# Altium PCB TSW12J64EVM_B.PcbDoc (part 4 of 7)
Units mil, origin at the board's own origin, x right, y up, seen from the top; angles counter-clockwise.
Board outline 8833 x 2680 mil, 10 copper layers (Top Layer L1, Gnd-Plane - L2, Signals - L3, Gnd-Plane - L4, Pwr Plane - L5, Signals - L6, Gnd-Plane - L7, Signals - L8, Gnd-Plane - L9, Bottom Layer - L10), stack 57.8 mil thick; 950 components, 533 nets, 2888 pads, 1732 vias.
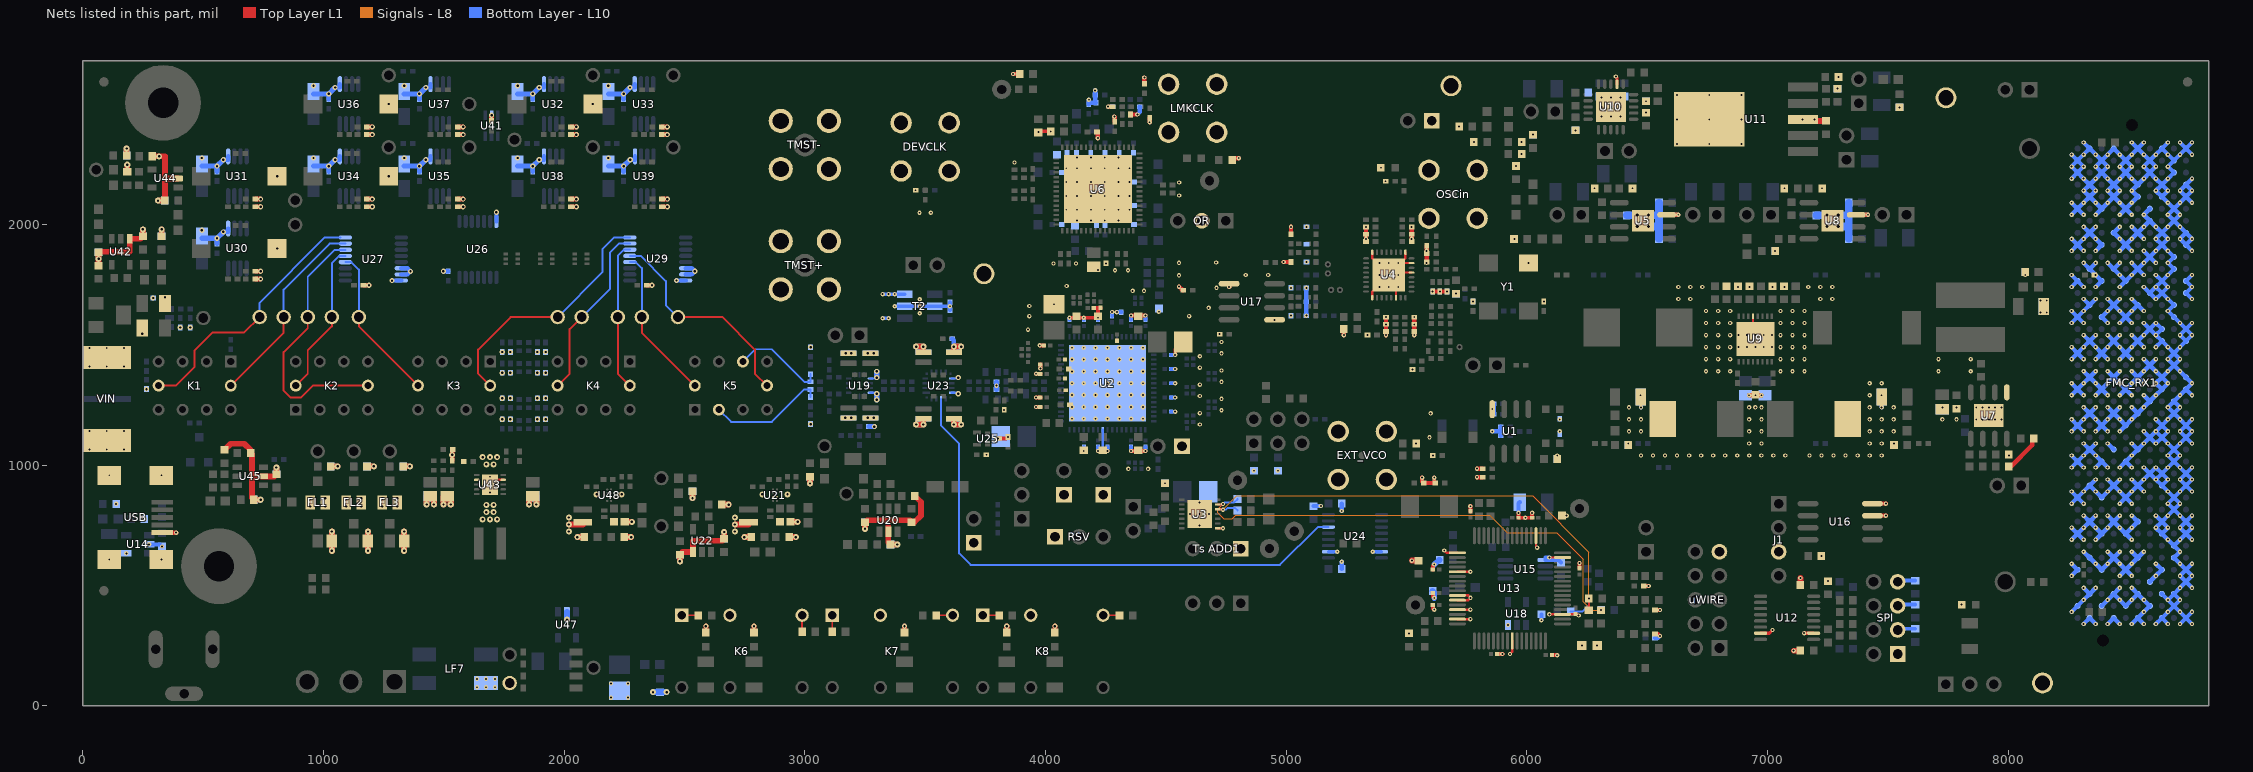
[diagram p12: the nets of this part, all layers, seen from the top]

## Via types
v1: diameter 18, hole 8, Top Layer L1 to Bottom Layer - L10, tented both sides, 1096 vias
v2: diameter 21.46, hole 10, Top Layer L1 to Bottom Layer - L10, tented both sides, 266 vias
v3: diameter 25, hole 10, Top Layer L1 to Bottom Layer - L10, tented both sides, 154 vias
v4: diameter 19.68, hole 7.87, Top Layer L1 to Bottom Layer - L10, 103 vias
v5: diameter 18, hole 8, Top Layer L1 to Bottom Layer - L10, tented bottom, 42 vias
v6: diameter 18, hole 8, Top Layer L1 to Bottom Layer - L10, tented top, 24 vias
v7: diameter 18, hole 8.01, Top Layer L1 to Bottom Layer - L10, tented both sides, 16 vias
v8: diameter 18, hole 8.01, Top Layer L1 to Bottom Layer - L10, tented bottom, 16 vias
v9: diameter 25.98, hole 12.99, Top Layer L1 to Bottom Layer - L10, tented top, 8 vias
v10: diameter 19.68, hole 7.87, Top Layer L1 to Bottom Layer - L10, tented top, 5 vias
v11: diameter 126, hole 106, Top Layer L1 to Bottom Layer - L10, tented top, 2 vias

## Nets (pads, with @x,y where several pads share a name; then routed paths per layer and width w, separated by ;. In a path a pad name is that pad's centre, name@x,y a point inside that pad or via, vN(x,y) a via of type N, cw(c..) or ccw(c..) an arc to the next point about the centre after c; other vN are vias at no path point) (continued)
GND: 1:1.1 2:1.1 5:1.1 12V.2 "1:1 Atten.2" "2:1 Atten.2" "5:1 Atten.2" "AC COUPLED.2" "DC COUPLED.2" "Ts ADD1.1" AC.1 C1.1 C2.2 C8.2 C11.2 C16.1 C18.1 C19.1 C24.2 C25.2 C27.2 C39.2 C40.2 C41.1 C42.1 C43.1 C44.1 C45.1 C46.1 C47.1 C48.2 C49.2 C50.2 C51.1 C52.1 C53.1 C54.1 C55.1 C56.1 C57.1 C58.1 C59.2 C60.2 C61.2 C62.1 C63.1 C64.1 C65.1 C66.1 C67.1 C68.1 C69.1 C70.1 C71.1 C72.2 C73.1 C74.1 C77.2 C78.2 C79.2 C80.2 C81.2 C82.2 C85.1 C88.2 C97.2 C98.2 C100.2 C102.2 C103.2 C104.2 C105.2 C106.2 C107.2 C108.2 C109.2 C110.2 C111.2 C114.1 C115.2 C116.2 C120.2 C121.2 C122.2 C124.2 C125.2 C126.2 C127.2 C128.2 C129.2 C130.2 C143.2 C144.2 C145.2 C146.2 C147.2 C150.2 C151.2 C152.2 C153.2 C155.2 C156.1 C157.1 C158.2 C159.2 C160.2 C161.2 C162.2 C163.2 C164.2 C165.2 C166.2 C167.2 C168.2 C171.2 C172.2 C173.2 C176.2 C177.2 C178.2 C179.2 C180.2 C181.2 C182.2 C183.2 C184.2 C185.2 C186.2 C187.2 C188.2 C189.2 C190.2 C191.2 C193.2 C194.2 C195.2 C196.2 C197.2 C198.2 C199.2 C202.2 C203.2 C204.2 C206.2 C207.2 C208.2 C209.2 C213.2 C215.2 C218.2 C228.2 C229.2 C230.2 C231.1 C232.2 C233.2 C234.2 C235.1 C236.2 C237.2 C238.2 C239.2 C240.2 C241.2 C242.2 C243.2 C250.1 C251.1 C252.2 C253.2 C254.2 C255.2 C256.2 C257.2 C258.1 C259.1 C260.1 C261.2 C264.1 C265.2 C266.2 C267.1 C268.2 C269.1 C270.1 C271.2 C272.1 C276.2 C277.2 C278.2 C280.2 C281.2 C282.2 C283.2 C284.1 C285.1 C287.2 C288.2 C289.2 C290.2 C291.2 C292.1 C297.2 C298.2 C299.2 C300.2 C301.1 C302.2 C303.2 C304.1 C305.2 C306.1 C307.1 C308.2 C309.1 C310.1 C311.2 C312.2 C313.2 C314.2 C315.2 C316.2 C317.2 C318.2 C319.2 C320.2 C321.2 C322.2 C323.2 C324.2 C325.2 C326.2 C327.2 C328.2 C329.2 C330.2 C331.1 C332.1 C333.1 C334.1 C335.1 C336.1 C337.1 C338.1 C339.1 C340.1 C346.2 C347.1 C349.1 C350.2 C351.2 C353.2 C354.2 C355.2 C356.2 C357.2 C358.2 C359.2 C360.2 C361.2 C362.2 C363.2 C364.2 C365.2 C366.2 C367.2 C368.2 C369.2 C370.1 C372.1 C373.1 C375.1 C376.2 C378.2 C379.1 C381.1 C382.2 C383.2 C384.2 C385.2 C386.1 C387.1 C388.1 C389.2 C390.2 C391.2 C392.2 C393.2 C394.1 C395.2 C396.2 C397.1 C398.2 C399.2 C400.1 C401.2 C402.2 C404.2 C405.2 C406.2 C407.2 C408.2 C410.2 C411.2 C413.2 C414.1 C415.2 C416.2 C418.1 C419.1 D5.2 D6.2 DC.1 DEVCLK.2 DEVCLK.3 DEVCLK.4 DEVCLK.5 EXT_Vcmo.1 EXT_VCO.2 EXT_VCO.3 EXT_VCO.4 EXT_VCO.5 FL1.2 FL2.2 FL3.2 FMC_RX1.A1 FMC_RX1.A4 FMC_RX1.A5 FMC_RX1.A8 FMC_RX1.A9 FMC_RX1.A12 FMC_RX1.A13 FMC_RX1.A16 FMC_RX1.A17 FMC_RX1.A20 FMC_RX1.A21 FMC_RX1.A24 FMC_RX1.A25 FMC_RX1.A28 FMC_RX1.A29 FMC_RX1.A32 FMC_RX1.A33 FMC_RX1.A36 FMC_RX1.A37 FMC_RX1.A40 FMC_RX1.B2 FMC_RX1.B3 FMC_RX1.B6 FMC_RX1.B7 FMC_RX1.B10 FMC_RX1.B11 FMC_RX1.B14 FMC_RX1.B15 FMC_RX1.B18 FMC_RX1.B19 FMC_RX1.B22 FMC_RX1.B23 FMC_RX1.B26 FMC_RX1.B27 FMC_RX1.B30 FMC_RX1.B31 FMC_RX1.B34 FMC_RX1.B35 FMC_RX1.B38 FMC_RX1.B39 FMC_RX1.C1 FMC_RX1.C4 FMC_RX1.C5 FMC_RX1.C8 FMC_RX1.C9 FMC_RX1.C12 FMC_RX1.C13 FMC_RX1.C16 FMC_RX1.C17 FMC_RX1.C20 FMC_RX1.C21 FMC_RX1.C24 FMC_RX1.C25 FMC_RX1.C28 FMC_RX1.C29 FMC_RX1.C32 FMC_RX1.C33 FMC_RX1.C36 FMC_RX1.C38 FMC_RX1.C40 FMC_RX1.D2 FMC_RX1.D3 FMC_RX1.D6 FMC_RX1.D7 FMC_RX1.D10 FMC_RX1.D13 FMC_RX1.D16 FMC_RX1.D19 FMC_RX1.D22 FMC_RX1.D25 FMC_RX1.D28 FMC_RX1.D37 FMC_RX1.D39 FMC_RX1.E1 FMC_RX1.E4 FMC_RX1.E5 FMC_RX1.E8 FMC_RX1.E11 FMC_RX1.E14 FMC_RX1.E17 FMC_RX1.E20 FMC_RX1.E23 FMC_RX1.E26 FMC_RX1.E29 FMC_RX1.E32 FMC_RX1.E35 FMC_RX1.E38 FMC_RX1.E40 FMC_RX1.F2 FMC_RX1.F3 FMC_RX1.F6 FMC_RX1.F9 FMC_RX1.F12 FMC_RX1.F15 FMC_RX1.F18 FMC_RX1.F21 FMC_RX1.F24 FMC_RX1.F27 FMC_RX1.F30 FMC_RX1.F33 FMC_RX1.F36 FMC_RX1.F39 FMC_RX1.G1 FMC_RX1.G4 FMC_RX1.G5 FMC_RX1.G8 FMC_RX1.G11 FMC_RX1.G14 FMC_RX1.G17 FMC_RX1.G20 FMC_RX1.G23 FMC_RX1.G26 FMC_RX1.G29 FMC_RX1.G32 FMC_RX1.G35 FMC_RX1.G38 FMC_RX1.G40 FMC_RX1.H2 FMC_RX1.H3 FMC_RX1.H6 FMC_RX1.H9 FMC_RX1.H12 FMC_RX1.H15 FMC_RX1.H18 FMC_RX1.H21 FMC_RX1.H24 FMC_RX1.H27 FMC_RX1.H30 FMC_RX1.H33 FMC_RX1.H36 FMC_RX1.H39 FMC_RX1.J1 FMC_RX1.J4 FMC_RX1.J5 FMC_RX1.J8 FMC_RX1.J11 FMC_RX1.J14 FMC_RX1.J17 FMC_RX1.J20 FMC_RX1.J23 FMC_RX1.J26 FMC_RX1.J29 FMC_RX1.J32 FMC_RX1.J35 FMC_RX1.J38 FMC_RX1.J40 FMC_RX1.K2 FMC_RX1.K3 FMC_RX1.K6 FMC_RX1.K9 FMC_RX1.K12 FMC_RX1.K15 FMC_RX1.K18 FMC_RX1.K21 FMC_RX1.K24 FMC_RX1.K27 FMC_RX1.K30 FMC_RX1.K33 FMC_RX1.K36 FMC_RX1.K39 GND1.1 GND2.1 GND3.1 GND4.1 GND.1 J1.3 K6.3 K7.3 K8.3 L23.2 L37.2 L41.2 LD.2 LF2.2 LF3.1 LF7.4 LMKCLK.2 LMKCLK.3 LMKCLK.4 LMKCLK.5 OR.2 OSCin.2 OSCin.3 OSCin.4 OSCin.5 R2.2 R3.1 R4.1 R5.1 R6.1 R10.2 R11.1 R12.1 R22.2 R23.2 R24.1 R26.1 R29.1 R30.1 R33.1 R36.1 R37.1 R45.1 R49.1 R50.2 R51.1 R56.1 R65.1 R76.1 R77.1 R86.1 R87.1 R88.1 R89.1 R90.1 R96.1 R104.1 R116.1 R122.1 R128.1 R129.1 R135.1 R139.1 R140.1 R141.1 R147.2 R152.2 R153.1 R158.1 R159.1 R165.1 R168.1 R172.1 R177.1 R186.1 R191.1 R193.1 R194.1 R196.1 R197.2 R199.2 R200.1 R202.1 R204.1 R232.1 R244.1 R247.1 R249.1 RSV.1 SPI.1 SPI.3 SPI.5 SPI.7 T2.1 T2.2 T2.5 TMST+.2 TMST+.3 TMST+.4 TMST+.5 TMST-.2 TMST-.3 TMST-.4 TMST-.5 U1.4 U2.61 U2.69 U3.8 U3.15 U4.1 U4.8 U4.17 U4.22 U4.29 U4.31 U4.33 U5.3 U5.9 U6.65 U7.5 U7.9 U8.3 U8.9 U9.5 U9.17 U10.12 U10.21 U11.3 U11.6 U12.7 U12.10 U16.3 U16.4 U17.1 U17.5 U18.3 U19.11 U19.14 U20.2 U21.C1 U21.C2 U22.1 U23.9 U23.12 U24.7 U24.10 U25.2 U26.7 U27.6 U27.7 U27.8 U29.6 U29.7 U29.8 U30.1 U31.1 U32.1 U33.1 U34.1 U35.1 U36.1 U37.1 U38.1 U39.1 U41.2 U42.1 U43.4 U43.7 U43.11 U44.2 U45.2 U47.2 U48.C1 U48.C2 uWIRE.9 VA12.1 VA19.1 Vbg.1 VD12.1 VIN.2 VIN.3 VIN.4 VIN.5 Y1.2 | length 31586
  Top Layer L1 w7: v3(3462.62,1168.6) C301.1@3462.62,1192.1 ; C307.1@3462.62,1468.22 v3(3462.62,1491.72) ; v3(3649.14,1168.6) C302.2@3649.14,1192.1 ; C308.2@3649.14,1468.22 v3(3649.14,1491.72)
  Top Layer L1 w9: U3.8@4715.08,737.7 v1(4737.28,737.7)
  Top Layer L1 w9.45: U43.11@1692,919 1711.68,938.68 U43.4@1747.12,938.68 ; U4.17@5357.34,1695.51 5357.34,1721.1 v4(5426.24,1790) ; U4.8@5357.34,1884.49 5357.34,1858.9 v4(5426.24,1790) ; U4.33@5436.08,1799.84 U4.29@5520.72,1799.84 ; U4.22@5455.76,1695.51 U4.33@5455.76,1760.47 ; U4.33@5475.45,1839.21 U4.31@5520.72,1839.21 ; U4.1@5495.13,1884.49 5495.13,1858.9 v4(5426.24,1790)
  Top Layer L1 w10: U9.5@6939.16,1618.49 6939.16,1553.53 U9.17@6949,1543.68
  Top Layer L1 w11.02: v4(5426.24,1790) U4.33@5455.76,1760.47
  Top Layer L1 w13: U12.7@6970.76,301.55 7007.03,301.55 v1(7020.48,315) ; v1(7151.68,301.55) U12.10@7191.24,301.55
  Top Layer L1 w13.5: v1(6369.77,2614.17) 6374.27,2609.67 U10.12@6374.27,2582.49
  Top Layer L1 w15: v1(3970.3,2383.18) 3973.86,2386.74 v1(4021.74,2386.74)
  Top Layer L1 w15.75: v1(3803.41,1110) 3837.23,1110 v1(3844.12,1116.89)
  Top Layer L1 w16: v1(3961.03,1241.58) C51.1@3978.65,1241.57 ; v1(3961.03,1280.95) C41.1@3978.65,1280.94 ; v1(3961.03,1379.37) C42.1@3978.65,1379.37 ; v1(3976.03,1497.48) C44.1@3993.65,1497.48 ; v1(3978.65,1401.47) C54.1@3978.65,1418.74 ; v1(4099.91,1612) v1(4218.02,1612) ; R22.2@4200.99,1653 R23.2@4229,1653.01 ; v1(4218.02,1058.65) v1(4257.39,1058.65) ; C50.2@4218.02,1618.3 4218.02,1653 ; v1(4355.81,1058.65) v1(4414.87,1058.65) ; v1(4355.81,1621.35) v1(4414.87,1621.35) ; v1(4538.74,1458.11) 4538.74,1477.62 C72.2@4572.52,1511.4
  Top Layer L1 w16.5: R116.1@6484.93,498 v1(6505.98,498) ; R128.1@6531.81,298 6544.87,298 v1(6552.87,290) ; R104.1@6531.81,398 v1(6552.87,398) ; U16.3@7435.86,790 v1(7491.16,790) ; U16.4@7435.86,840 v1(7491.16,840)
  Top Layer L1 w18: v1(3865.3,2625) R45.1@3892.94,2625 ; C85.1@4213.69,2384 4217.56,2380.13 v1(4217.56,2358.32) ; v1(4260.43,2489) R50.2@4279.3,2489 ; v1(4286.16,2447.5) 4288,2445.65 C88.2@4288,2426.69 ; C114.1@4352.67,2456.68 v1(4381.54,2456.69) ; C259.1@4410.91,2584.24 v1(4410.91,2610.11) ; v1(4432.67,2424.26) R51.1@4432.67,2443.13 ; v1(4554.36,1741.48) 4569.84,1726 C215.2@4572.31,1726 ; v1(4762.84,1740) U17.5@4762.84,1753.5 ; R56.1@4775.06,2274.95 v1(4802.7,2274.95) ; v1(4989.23,1843.81) R36.1@5020.05,1843.81 ; R29.1@5020.05,1959.18 v1(5020.05,1990) ; v1(5239.44,1540) R152.2@5239.44,1565 ; C257.2@5331.35,1929.09 C256.2@5331.35,1959.09 v1(5331.35,1989.09) ; v1(5414.55,1540) C243.2@5414.55,1554.68 v1(5414.55,1614.68) ; C254.2@5521.12,1929.09 C253.2@5521.12,1959.09 v1(5521.12,1989.09) ; v1(5531.92,1540) C240.2@5531.92,1554.68 v1(5531.92,1614.68) ; v1(5608.33,1721.1) v1(5668.33,1721.1) ; v1(5792.82,950) R11.1@5816.63,950 ; v1(5792.82,985) C8.2@5816.63,985 ; U5.3@6580.43,2040 v1(6628.8,2040) ; v1(6923.47,1290) v1(6974.53,1290) ; U8.3@7368.43,2040 v1(7416.8,2040) ; R76.1@8002.56,995 8012,995 8099,1082 8099,1101.98 C162.2@8106.56,1109.54
  Top Layer L1 w19.68: C321.2@716.69,1773.13 v2(739.23,1773.13) ; C311.2@716.69,1805 v2(739.23,1805) ; C322.2@716.69,2073.13 v2(739.23,2073.13) ; C312.2@716.69,2105 v2(739.23,2105) ; C347.1@1166.68,1746.84 v2(1189.23,1746.84) ; C325.2@1180.69,2073.13 v2(1203.23,2073.13) ; C315.2@1180.69,2105 v2(1203.23,2105) ; C327.2@1180.69,2373.13 v2(1203.23,2373.13) ; C317.2@1180.69,2405 v2(1203.23,2405) ; R244.1@1535,1018.37 v3(1535,1042.68) 1535,1062.97 C385.2@1537.06,1065.02 ; C326.2@1557.69,2073.13 v2(1580.23,2073.13) ; C316.2@1557.69,2105 v2(1580.23,2105) ; C328.2@1557.69,2373.13 v2(1580.23,2373.13) ; C318.2@1557.69,2405 v2(1580.23,2405) ; C355.2@1698.58,2429.69 v2(1698.58,2453.4) ; C329.2@2028.69,2073.13 v2(2051.23,2073.13) ; C319.2@2028.69,2105 v2(2051.23,2105) ; C323.2@2028.69,2373.13 v2(2051.23,2373.13) ; C313.2@2028.69,2405 v2(2051.23,2405) ; C349.1@2342.68,1746.84 v2(2365.23,1746.84) ; C324.2@2405.69,2373.13 v2(2428.23,2373.13) ; C314.2@2405.69,2405 v2(2428.23,2405) ; C330.2@2406.69,2073.13 v2(2429.23,2073.13) ; C320.2@2406.69,2105 v2(2429.23,2105) ; C251.1@5583.65,1844 R30.1@5583.65,1911.41
  Top Layer L1 w21.46: 2589,304.53 v2(2589,331.01) ; 2789,304.53 v2(2789,331.01) ; 3414,304.53 v2(3414,331.01) ; 3839,304.53 v2(3839,331.01) ; 4039,304.53 v2(4039,331.01)
  Top Layer L1 w22: v3(3492.62,1168.6) C301.1@3492.62,1192.1 ; C307.1@3492.62,1468.22 v3(3492.62,1491.72) ; v3(3619.14,1168.6) C302.2@3619.15,1192.09 ; C308.2@3619.15,1468.22 v3(3619.14,1491.72)
  Top Layer L1 w23.62: C357.2@66,1886 195.4,1886 U42.1@195.4,1940.13 239.37,1940.13 C359.2@250,1950.76 ; R247.1@289.23,2283 342,2283 342,2191 ; C390.2@342,2099 342,2191 ; U44.2@396.13,2191 342,2191
  Top Layer L1 w24: R232.1@66,1828.52 v3(66,1856.77) C357.2@66,1885.02 ; C392.2@182.12,2286.98 v3(182.12,2315.23) ; C393.2@185,2219.54 v3(185,2247.79) ; C359.2@250,1950.76 v3(250,1979.01) ; v3(312.77,2099) C390.2@341.02,2099 ; C405.2@328,1950.76 v3(328,1979.01) ; R249.1@589.11,1063.56 614.55,1089 671.18,1089 697.98,1062.2 C408.2@697.98,1050 703,1044.98 703,863.87 C411.2@710.87,856 v3(739.12,856) ; 703,953 U45.2@751.13,953 796.03,953 C407.2@804.89,961.86 v3(804.89,990.11) ; C396.2@1031.12,995 v3(1059.37,995) ; C402.2@1181.12,995 v3(1209.37,995) ; C399.2@1331.12,995 v3(1359.37,995) ; v3(2055.37,701.02) C418.1@2083.62,701.02 ; C419.1@2250.36,701.02 v3(2278.6,701.02) ; C415.2@2251.99,764.47 v3(2281.22,764.47) ; v3(2481,599.88) C300.2@2481,628.13 2491.63,638.76 U22.1@2535.6,638.76 2535.6,686 2657.13,686 C288.2@2665,693.87 v3(2665,722.12) ; v3(2533.47,862.65) C289.2@2533.47,890.9 ; R177.1@2655.68,836 v3(2683.93,836) ; v3(2749.18,701.02) C284.1@2777.43,701.02 ; C285.1@2934.55,701.02 v3(2962.8,701.02) ; C282.2@2940.99,764.46 v3(2970.22,764.46) ; v3(3021.57,923.6) C281.2@3021.57,951.85 ; v3(3250,734.88) C298.2@3250,763.13 3257.87,771 3347,771 ; v3(3384.11,670) C277.2@3355.86,670 3347,678.86 U20.2@3347,723.76 3347,771 ; R172.1@3457.56,872 3483,846.56 3483,789.93 3456.2,763.13 C278.2@3444,763.13 3436.13,771 3347,771 ; v1(7108.37,229) R65.1@7136.12,229 ; C129.2@7136.12,502.06 v1(7136.12,530.79) ; U11.3@7147.22,2436 7153.13,2430.09 C196.2@7243,2430.09
  Top Layer L1 w25: v3(1035.06,644.11) C394.1@1035.06,684.17 v3(1035.06,724.23) ; v3(1185.05,644.11) C400.1@1185.05,684.17 v3(1185.05,724.23) ; v3(1335.05,644.11) C397.1@1335.05,684.17 v3(1335.05,724.23) ; v3(1428.94,836.32) C387.1@1428.94,870.47 ; v3(1459.06,836.32) C387.1@1459.06,870.47 ; v3(1498.94,836.32) C386.1@1498.94,870.47 ; v3(1529.06,836.32) C386.1@1529.06,870.47 ; v3(1854.94,836.32) C383.2@1854.94,870.47 ; v3(1885.06,836.32) C383.2@1885.06,870.47 ; v3(2019.99,753.16) L41.2@2077.49,753.16 ; v3(2708.99,753.16) L37.2@2766.49,753.16 ; v3(3462.62,1168.6) v3(3492.62,1168.6) ; v3(3462.62,1491.72) v3(3492.62,1491.72) ; v3(3619.14,1168.6) v3(3649.14,1168.6) ; v3(3619.14,1491.72) v3(3649.14,1491.72)
  Bottom Layer - L10 w7: v3(3462.62,1168.6) C303.2@3462.62,1192.1 ; C305.2@3462.62,1468.22 v3(3462.62,1491.72) ; v3(3649.14,1168.6) C304.1@3649.14,1192.1 ; C306.1@3649.14,1468.22 v3(3649.14,1491.72)
  Bottom Layer - L10 w9: 4237.7,1058.65 U2.61@4237.7,1147.09
  Bottom Layer - L10 w9.84: U19.14@3272.5,1300.63 3295.01,1300.63 v2(3298.98,1296.66) ; U19.11@3272.5,1359.68 3295.01,1359.68 v2(3298.98,1363.65) ; U23.12@3611,1300.63 3633.51,1300.63 v2(3637.48,1296.66) ; U23.9@3611,1359.68 3633.51,1359.68 v2(3637.48,1363.65)
  Bottom Layer - L10 w13: U24.10@5175.57,640.02 v1(5212.13,640.02) ; v1(5359.49,640.02) U24.7@5396.05,640.02
  Bottom Layer - L10 w16: v1(3323.58,1609.95) v1(3348.58,1609.95) ; v1(3323.58,1709.95) T2.1@3415.06,1709.95 ; v1(3373.58,1659.95) v1(3602.85,1659.95) ; C229.2@3602.85,1643.14 v1(3602.85,1659.95) ; C228.2@3602.85,1676.76 v1(3602.85,1659.95) ; C45.1@4099.91,1603.73 v1(4099.91,1612) ; v1(4158.96,1058.65) C47.1@4158.96,1076.27 ; C46.1@4158.96,1603.73 v1(4158.96,1612) ; C58.1@4218.02,1076.27 v1(4218.02,1058.65) v1(4257.39,1058.65) C57.1@4257.39,1076.27 ; C55.1@4218.02,1603.73 v1(4218.02,1612) ; C56.1@4277.07,1618.73 v1(4277.07,1636.35) ; v1(4296.16,1635.31) C16.1@4315,1635.31 ; v1(4355.81,1058.65) C62.1@4355.81,1076.27 ; C70.1@4355.81,1603.73 v1(4355.81,1621.35) ; v1(4414.87,1058.65) C63.1@4414.87,1076.27 ; C69.1@4414.87,1603.73 v1(4414.87,1621.35) ; C64.1@4521.12,1221.89 v1(4538.74,1221.89) ; C65.1@4521.12,1280.95 v1(4538.74,1280.94) ; C66.1@4521.12,1340 v1(4538.74,1340) ; C67.1@4521.12,1399.05 v1(4538.74,1399.05) ; C68.1@4521.12,1458.11 v1(4538.74,1458.11) ; SPI.3@7540,315 7545.12,320.12 R139.1@7613.44,320.12 ; SPI.5@7540,415 7545.12,420.12 R140.1@7613.44,420.12 ; SPI.7@7540,515 7545.12,520.12 R141.1@7613.44,520.12
  Bottom Layer - L10 w16.5: v1(6060,355.39) C213.2@6060,380.13 ; R129.1@6531.81,282 6544.87,282 v1(6552.87,290)
  Bottom Layer - L10 w17.72: v2(584.66,1968.88) 604.25,1968.88 U30.1@604.25,1982.68 ; v2(584.66,2268.88) 604.25,2268.88 U31.1@604.25,2282.68 ; v2(1048.66,2268.88) 1068.25,2268.88 U34.1@1068.25,2282.68 ; v2(1048.66,2568.88) 1068.25,2568.88 U36.1@1068.25,2582.68 ; v2(1285.13,1766.43) U27.8@1323.43,1766.43 ; U27.7@1323.43,1792.02 1348.92,1792.02 v2(1361.72,1804.82) 1348.92,1817.61 U27.6@1323.43,1817.61 ; v2(1425.66,2268.88) 1445.25,2268.88 U35.1@1445.25,2282.68 ; v2(1425.66,2568.88) 1445.25,2568.88 U37.1@1445.25,2582.68 ; U26.7@1718.77,2012.14 v2(1718.77,2050.43) ; v2(1896.66,2268.88) 1916.25,2268.88 U38.1@1916.25,2282.68 ; v2(1896.66,2568.88) 1916.25,2568.88 U32.1@1916.25,2582.68 ; v2(2273.66,2568.88) 2293.25,2568.88 U33.1@2293.25,2582.68 ; v2(2274.66,2268.88) 2294.25,2268.88 U39.1@2294.25,2282.68 ; v2(2466.99,1766.87) U29.8@2505.28,1766.87 ; U29.7@2505.28,1792.46 2530.78,1792.46 v2(2543.57,1805.25) 2530.78,1818.05 U29.6@2505.28,1818.05
  Bottom Layer - L10 w18: C107.2@4179.92,2498.87 v1(4179.92,2517.74) ; C107.2@4179.92,2505.74 C104.2@4210.05,2505.74 4206.31,2509.47 C260.1@4206.31,2537.87 v1(4206.32,2556.74) ; v1(4260.43,2489) R159.1@4279.3,2489 ; v1(4381.54,2456.69) 4392.04,2467.19 R158.1@4392.04,2489 ; C98.2@5113.28,829.84 v1(5143.83,829.84) ; R186.1@5230.69,568 v1(5230.69,598.54) ; v1(5230.69,809.46) C97.2@5230.69,840 ; v1(6474,1240) C183.2@6474,1290 ; 6548.93,2040 v1(6628.8,2040) ; 7336.93,2040 v1(7416.8,2040) ; v1(7473.85,1240) v1(7473.85,1290) ; v1(8263,390) FMC_RX1.K39@8288,415 v1(8313,440) FMC_RX1.J38@8338,465 ; v1(8263,540) FMC_RX1.K36@8288,565 v1(8263,590) ; v1(8263,690) FMC_RX1.K33@8288,715 ; v1(8263,740) FMC_RX1.K33@8288,715 ; v1(8263,840) FMC_RX1.K30@8288,865 ; v1(8263,890) FMC_RX1.K30@8288,865 ; v1(8263,990) FMC_RX1.K27@8288,1015 ; v1(8263,1040) FMC_RX1.K27@8288,1015 ; v1(8263,1140) FMC_RX1.K24@8288,1165 ; v1(8263,1190) FMC_RX1.K24@8288,1165 ; v1(8263,1290) FMC_RX1.K21@8288,1315 ; v1(8263,1340) FMC_RX1.K21@8288,1315 ; v1(8263,1440) FMC_RX1.K18@8288,1465 ; v1(8263,1490) FMC_RX1.K18@8288,1465 ; v1(8263,1590) FMC_RX1.K15@8288,1615 ; v1(8263,1640) FMC_RX1.K15@8288,1615 ; v1(8263,1740) FMC_RX1.K12@8288,1765 ; v1(8263,1790) FMC_RX1.K12@8288,1765 ; v1(8263,1890) FMC_RX1.K9@8288,1915 ; v1(8263,1940) FMC_RX1.K9@8288,1915 ; v1(8263,2040) FMC_RX1.K6@8288,2065 ; v1(8263,2090) FMC_RX1.K6@8288,2065 ; v1(8263,2190) FMC_RX1.K3@8288,2215 ; v1(8263,2290) FMC_RX1.K2@8288,2265 ; v1(8313,340) FMC_RX1.J40@8338,365 v1(8363,340) ; v1(8313,490) FMC_RX1.J38@8338,465 ; v1(8313,640) FMC_RX1.J35@8338,615 v1(8363,590) FMC_RX1.H36@8388,565 v1(8413,590) FMC_RX1.G35@8438,615 ; v1(8313,690) FMC_RX1.K33@8288,715 ; v1(8313,790) FMC_RX1.J32@8338,765 ; v1(8313,840) FMC_RX1.K30@8288,865 ; v1(8313,990) FMC_RX1.K27@8288,1015 ; v1(8313,1090) FMC_RX1.J26@8338,1065 ; v1(8313,1140) FMC_RX1.K24@8288,1165 ; v1(8313,1240) FMC_RX1.J23@8338,1215 ; v1(8313,1290) FMC_RX1.K21@8288,1315 ; v1(8313,1390) FMC_RX1.J20@8338,1365 ; v1(8313,1440) FMC_RX1.K18@8288,1465 ; v1(8313,1540) FMC_RX1.J17@8338,1515 ; v1(8313,1590) FMC_RX1.K15@8288,1615 ; v1(8313,1690) FMC_RX1.J14@8338,1665 ; v1(8313,1740) FMC_RX1.K12@8288,1765 ; v1(8313,1840) FMC_RX1.J11@8338,1815 ; v1(8313,1890) FMC_RX1.K9@8288,1915 ; v1(8313,1990) FMC_RX1.J8@8338,1965 ; v1(8313,2040) FMC_RX1.K6@8288,2065 ; v1(8313,2340) FMC_RX1.J1@8338,2315 ; v1(8363,490) FMC_RX1.J38@8338,465 ; v1(8363,690) FMC_RX1.H33@8388,715 ; v1(8363,790) FMC_RX1.J32@8338,765 ; v1(8363,940) FMC_RX1.J29@8338,915 ; v1(8363,990) FMC_RX1.H27@8388,1015 ; v1(8363,1090) FMC_RX1.J26@8338,1065 ; v1(8363,1140) FMC_RX1.H24@8388,1165 ; v1(8363,1240) FMC_RX1.J23@8338,1215 ; v1(8363,1290) FMC_RX1.H21@8388,1315 ; v1(8363,1390) FMC_RX1.J20@8338,1365 ; v1(8363,1440) FMC_RX1.H18@8388,1465 ; v1(8363,1540) FMC_RX1.J17@8338,1515 ; v1(8363,1690) FMC_RX1.J14@8338,1665 ; v1(8363,1740) FMC_RX1.H12@8388,1765 v1(8363,1790) FMC_RX1.J11@8338,1815 ; v1(8363,1840) FMC_RX1.J11@8338,1815 ; v1(8363,1890) FMC_RX1.H9@8388,1915 v1(8363,1940) FMC_RX1.J8@8338,1965 ; v1(8363,1990) FMC_RX1.J8@8338,1965 ; v1(8363,2040) FMC_RX1.H6@8388,2065 ; FMC_RX1.H39@8388,415 v1(8413,440) FMC_RX1.G38@8438,465 ; v1(8413,340) FMC_RX1.G40@8438,365 v1(8463,340) ; v1(8413,640) FMC_RX1.G35@8438,615 ; v1(8413,790) FMC_RX1.G32@8438,765 ; v1(8413,940) FMC_RX1.G29@8438,915 ; v1(8413,990) FMC_RX1.H27@8388,1015 ; v1(8413,1090) FMC_RX1.G26@8438,1065 ; v1(8413,1140) FMC_RX1.H24@8388,1165 ; v1(8413,1240) FMC_RX1.G23@8438,1215 ; v1(8413,1290) FMC_RX1.H21@8388,1315 ; v1(8413,1390) FMC_RX1.G20@8438,1365 ; v1(8413,1440) FMC_RX1.H18@8388,1465 ; v1(8413,1540) FMC_RX1.G17@8438,1515 ; v1(8413,1590) FMC_RX1.H15@8388,1615 v1(8413,1640) FMC_RX1.G14@8438,1665 ; v1(8413,1690) FMC_RX1.G14@8438,1665 ; v1(8413,1840) FMC_RX1.G11@8438,1815 ; v1(8463,490) FMC_RX1.G38@8438,465 ; v1(8463,540) FMC_RX1.F36@8488,565 ; v1(8463,640) FMC_RX1.G35@8438,615 ; v1(8463,790) FMC_RX1.G32@8438,765 ; v1(8463,840) FMC_RX1.F30@8488,865 ; v1(8463,940) FMC_RX1.G29@8438,915 ; v1(8463,990) FMC_RX1.F27@8488,1015 ; v1(8463,1140) FMC_RX1.F24@8488,1165 ; v1(8463,1240) FMC_RX1.G23@8438,1215 ; v1(8463,1290) FMC_RX1.F21@8488,1315 ; v1(8463,1390) FMC_RX1.G20@8438,1365 ; v1(8463,1440) FMC_RX1.F18@8488,1465 ; v1(8463,1540) FMC_RX1.G17@8438,1515 ; v1(8463,1590) FMC_RX1.F15@8488,1615 ; v1(8463,1690) FMC_RX1.G14@8438,1665 ; v1(8463,1740) FMC_RX1.F12@8488,1765 ; v1(8463,1840) FMC_RX1.G11@8438,1815 ; v1(8463,1890) FMC_RX1.F9@8488,1915 ; v1(8463,1990) FMC_RX1.G8@8438,1965 v1(8463,1940) FMC_RX1.F9@8488,1915 ; v1(8463,2040) FMC_RX1.F6@8488,2065 ; FMC_RX1.F9@8486,1913 v1@8511,1938 ; v1(8513,340) FMC_RX1.E40@8538,365 ; v1(8513,490) FMC_RX1.E38@8538,465 ; v1(8513,540) FMC_RX1.F36@8488,565 ; v1(8513,640) FMC_RX1.E35@8538,615 ; v1(8513,690) FMC_RX1.F33@8488,715 ; v1(8513,790) FMC_RX1.E32@8538,765 v1(8513,740) FMC_RX1.F33@8488,715 ; v1(8513,840) FMC_RX1.F30@8488,865 ; v1(8513,940) FMC_RX1.E29@8538,915 ; v1(8513,990) FMC_RX1.F27@8488,1015 ; v1(8513,1090) FMC_RX1.E26@8538,1065 ; v1(8513,1240) FMC_RX1.E23@8538,1215 ; v1(8513,1290) FMC_RX1.F21@8488,1315 ; v1(8513,1390) FMC_RX1.E20@8538,1365 ; v1(8513,1440) FMC_RX1.F18@8488,1465 ; v1(8513,1540) FMC_RX1.E17@8538,1515 ; v1(8513,1590) FMC_RX1.F15@8488,1615 ; v1(8513,1690) FMC_RX1.E14@8538,1665 ; v1(8513,1840) FMC_RX1.E11@8538,1815 ; v1(8513,1890) FMC_RX1.F9@8488,1915 ; v1(8513,1940) FMC_RX1.E8@8538,1965 ; v1(8513,1990) FMC_RX1.E8@8538,1965 ; v1(8513,2040) FMC_RX1.F6@8488,2065 ; v1(8513,2340) FMC_RX1.E1@8538,2315 ; v1(8563,340) FMC_RX1.E40@8538,365 ; v1(8563,640) FMC_RX1.E35@8538,615 ; v1(8563,890) FMC_RX1.E29@8538,915 ; v1(8563,990) FMC_RX1.D28@8588,965 ; v1(8563,1140) FMC_RX1.D25@8588,1115 ; v1(8563,1290) FMC_RX1.D22@8588,1265 ; v1(8563,1340) FMC_RX1.E20@8538,1365 ; v1(8563,1440) FMC_RX1.D19@8588,1415 ; v1(8563,1490) FMC_RX1.E17@8538,1515 ; v1(8563,1590) FMC_RX1.D16@8588,1565 ; v1(8563,1640) FMC_RX1.E14@8538,1665 ; v1(8563,1740) FMC_RX1.D13@8588,1715 ; v1(8563,1790) FMC_RX1.E11@8538,1815 ; v1(8563,1890) FMC_RX1.D10@8588,1865 ; v1(8563,1940) FMC_RX1.E8@8538,1965 ; v1(8563,2340) FMC_RX1.E1@8538,2315 ; FMC_RX1.D37@8588,515 v1(8613,540) FMC_RX1.C36@8638,565 v1(8613,590) ; FMC_RX1.D6@8588,2065 v1(8563,2040) FMC_RX1.D7@8588,2015 ; v1(8613,340) FMC_RX1.C40@8638,365 ; v1(8613,790) FMC_RX1.C32@8638,765 ; v1(8613,1140) FMC_RX1.D25@8588,1115 ; v1(8613,1190) FMC_RX1.C24@8638,1165 ; v1(8613,1440) FMC_RX1.D19@8588,1415 ; v1(8613,1490) FMC_RX1.C17@8638,1515 ; v1(8613,1790) FMC_RX1.C12@8638,1765 ; v1(8613,1840) FMC_RX1.D10@8588,1865 ; FMC_RX1.C38@8638,465 v1(8663,440) ; FMC_RX1.C25@8639,1115 8614,1140 FMC_RX1.C24@8639,1165 ; v1(8663,340) FMC_RX1.C40@8638,365 ; v1(8663,1440) FMC_RX1.B18@8688,1465 ; v1(8663,2340) FMC_RX1.C1@8638,2315 ; v1@8667,1436 FMC_RX1.B19@8692,1411 ; v1(8713,340) FMC_RX1.A40@8738,365 ; v1(8713,2340) FMC_RX1.A1@8738,2315 ; v1(8763,340) FMC_RX1.A40@8738,365 ; v1(8763,390) FMC_RX1.A40@8738,365 ; v1(8763,490) FMC_RX1.A37@8738,515 ; v1(8763,590) FMC_RX1.A36@8738,565 ; v1(8763,690) FMC_RX1.A33@8738,715 ; v1(8763,790) FMC_RX1.A32@8738,765 ; v1(8763,890) FMC_RX1.A29@8738,915 ; v1(8763,990) FMC_RX1.A28@8738,965 ; v1(8763,1090) FMC_RX1.A25@8738,1115 ; v1(8763,1190) FMC_RX1.A24@8738,1165 ; v1(8763,1290) FMC_RX1.A21@8738,1315 ; v1(8763,1590) FMC_RX1.A16@8738,1565 ; v1(8763,1690) FMC_RX1.A13@8738,1715 v1(8763,1740) FMC_RX1.A12@8738,1765 v1(8763,1790) ; v1(8763,1890) FMC_RX1.A9@8738,1915 ; v1(8763,2090) FMC_RX1.A5@8738,2115 ; v1(8763,2190) FMC_RX1.A4@8738,2165 ; v1(8763,2290) FMC_RX1.A1@8738,2315 ; v1(8763,2340) FMC_RX1.A1@8738,2315 ; FMC_RX1.K33@8288,715 v1(8313,740) FMC_RX1.J32@8338,765 ; FMC_RX1.K30@8288,865 v1(8313,890) FMC_RX1.J29@8338,915 ; FMC_RX1.K27@8288,1015 v1(8313,1040) FMC_RX1.J26@8338,1065 ; FMC_RX1.K24@8288,1165 v1(8313,1190) FMC_RX1.J23@8338,1215 ; FMC_RX1.K21@8288,1315 v1(8313,1340) FMC_RX1.J20@8338,1365 ; FMC_RX1.K18@8288,1465 v1(8313,1490) FMC_RX1.J17@8338,1515 ; FMC_RX1.K15@8288,1615 v1(8313,1640) FMC_RX1.J14@8338,1665 ; FMC_RX1.K9@8288,1915 v1(8313,1940) FMC_RX1.J8@8338,1965 ; FMC_RX1.K6@8288,2065 v1(8313,2090) FMC_RX1.J5@8338,2115 ; FMC_RX1.K3@8288,2215 v1(8263,2240) FMC_RX1.K2@8288,2265 ; FMC_RX1.K3@8288,2215 v1(8313,2190) FMC_RX1.J4@8338,2165 ; FMC_RX1.K3@8288,2215 v1(8313,2240) FMC_RX1.K2@8288,2265 ; FMC_RX1.K2@8288,2265 v1(8313,2290) FMC_RX1.J1@8338,2315 ; FMC_RX1.J32@8338,765 v1(8363,740) FMC_RX1.H33@8388,715 ; FMC_RX1.J29@8338,915 v1(8363,890) FMC_RX1.H30@8388,865 v1(8413,890) FMC_RX1.G29@8438,915 ; FMC_RX1.J26@8338,1065 v1(8363,1040) FMC_RX1.H27@8388,1015 ; FMC_RX1.J23@8338,1215 v1(8363,1190) FMC_RX1.H24@8388,1165 ; FMC_RX1.J20@8338,1365 v1(8363,1340) FMC_RX1.H21@8388,1315 ; FMC_RX1.J17@8338,1515 v1(8363,1490) FMC_RX1.H18@8388,1465 ; FMC_RX1.J5@8338,2115 v1(8363,2090) FMC_RX1.H6@8388,2065 ; FMC_RX1.J5@8338,2115 v1(8313,2140) FMC_RX1.J4@8338,2165 ; FMC_RX1.J5@8338,2115 v1(8363,2140) FMC_RX1.J4@8338,2165 ; FMC_RX1.J4@8338,2165 v1(8363,2190) FMC_RX1.H3@8388,2215 ; FMC_RX1.J1@8338,2315 v1(8363,2290) FMC_RX1.H2@8388,2265 ; FMC_RX1.H33@8388,715 v1(8413,740) FMC_RX1.G32@8438,765 ; FMC_RX1.H24@8388,1165 v1(8413,1190) FMC_RX1.G23@8438,1215 ; FMC_RX1.H21@8388,1315 v1(8413,1340) FMC_RX1.G20@8438,1365 ; FMC_RX1.H18@8388,1465 v1(8413,1490) FMC_RX1.G17@8438,1515 ; FMC_RX1.H6@8388,2065 v1(8413,2090) FMC_RX1.G5@8438,2115 ; FMC_RX1.H3@8388,2215 v1(8413,2240) FMC_RX1.H2@8388,2265 ; FMC_RX1.H3@8388,2215 v1(8413,2190) FMC_RX1.G4@8438,2165 ; FMC_RX1.H3@8388,2215 v1(8363,2240) FMC_RX1.H2@8388,2265 ; FMC_RX1.H2@8388,2265 v1(8413,2290) FMC_RX1.G1@8438,2315 v1(8463,2290) FMC_RX1.F2@8488,2265 ; FMC_RX1.G38@8438,465 v1(8463,440) FMC_RX1.F39@8488,415 v1(8513,440) FMC_RX1.E38@8538,465 ; FMC_RX1.G35@8438,615 v1(8463,590) FMC_RX1.F36@8488,565 ; FMC_RX1.G32@8438,765 v1(8463,740) FMC_RX1.F33@8488,715 ; FMC_RX1.G29@8438,915 v1(8463,890) FMC_RX1.F30@8488,865 ; FMC_RX1.G23@8438,1215 v1(8463,1190) FMC_RX1.F24@8488,1165 ; FMC_RX1.G20@8438,1365 v1(8463,1340) FMC_RX1.F21@8488,1315 ; FMC_RX1.G17@8438,1515 v1(8463,1490) FMC_RX1.F18@8488,1465 ; FMC_RX1.G14@8438,1665 v1(8463,1640) FMC_RX1.F15@8488,1615 ; FMC_RX1.G11@8438,1815 v1(8463,1790) FMC_RX1.F12@8488,1765 ; FMC_RX1.G5@8438,2115 v1(8463,2090) FMC_RX1.F6@8488,2065 ; FMC_RX1.G5@8438,2115 v1(8413,2140) FMC_RX1.G4@8438,2165 ; FMC_RX1.G5@8438,2115 v1(8463,2140) FMC_RX1.G4@8438,2165 ; FMC_RX1.G4@8438,2165 v1(8463,2190) FMC_RX1.F3@8488,2215 ; FMC_RX1.F36@8488,565 v1(8513,590) FMC_RX1.E35@8538,615 ; FMC_RX1.F30@8488,865 v1(8513,890) FMC_RX1.E29@8538,915 ; FMC_RX1.F27@8488,1015 v1(8513,1040) FMC_RX1.E26@8538,1065 ; FMC_RX1.F24@8488,1165 v1(8513,1190) FMC_RX1.E23@8538,1215 ; FMC_RX1.F21@8488,1315 v1(8513,1340) FMC_RX1.E20@8538,1365 ; FMC_RX1.F18@8488,1465 v1(8513,1490) FMC_RX1.E17@8538,1515 ; FMC_RX1.F15@8488,1615 v1(8513,1640) FMC_RX1.E14@8538,1665 ; FMC_RX1.F12@8488,1765 v1(8513,1790) FMC_RX1.E11@8538,1815 ; FMC_RX1.F6@8488,2065 v1(8513,2090) FMC_RX1.E5@8538,2115 v1(8513,2140) FMC_RX1.E4@8538,2165 ; FMC_RX1.F3@8488,2215 v1(8513,2190) FMC_RX1.E4@8538,2165 ; FMC_RX1.F3@8488,2215 v1(8463,2240) FMC_RX1.F2@8488,2265 ; FMC_RX1.F3@8488,2215 v1(8513,2240) FMC_RX1.F2@8488,2265 ; FMC_RX1.F2@8488,2265 v1(8513,2290) FMC_RX1.E1@8538,2315 ; FMC_RX1.E40@8538,365 v1(8563,390) FMC_RX1.D39@8588,415 v1(8563,440) FMC_RX1.E38@8538,465 ; FMC_RX1.E29@8538,915 v1(8563,940) FMC_RX1.D28@8588,965 ; FMC_RX1.E26@8538,1065 v1(8563,1090) FMC_RX1.D25@8588,1115 ; FMC_RX1.E23@8538,1215 v1(8563,1240) FMC_RX1.D22@8588,1265 ; FMC_RX1.E20@8538,1365 v1(8563,1390) FMC_RX1.D19@8588,1415 ; FMC_RX1.E17@8538,1515 v1(8563,1540) FMC_RX1.D16@8588,1565 ; FMC_RX1.E11@8538,1815 v1(8563,1840) FMC_RX1.D10@8588,1865 ; FMC_RX1.E8@8538,1965 v1(8563,1990) FMC_RX1.D7@8588,2015 ; FMC_RX1.E4@8538,2165 v1(8563,2190) FMC_RX1.D3@8588,2215 ; FMC_RX1.E1@8538,2315 v1(8563,2290) FMC_RX1.D2@8588,2265 ; FMC_RX1.D28@8588,965 v1(8613,940) ; FMC_RX1.D28@8588,965 v1(8613,990) FMC_RX1.C28@8638,965 ; FMC_RX1.D25@8588,1115 v1(8613,1090) FMC_RX1.C25@8638,1115 ; FMC_RX1.D22@8588,1265 v1(8613,1290) FMC_RX1.C21@8638,1315 ; FMC_RX1.D19@8588,1415 v1(8613,1390) FMC_RX1.C20@8638,1365 ; FMC_RX1.D16@8588,1565 v1(8613,1540) ; FMC_RX1.D16@8588,1565 v1(8613,1590) FMC_RX1.C16@8638,1565 v1(8613,1540) ; FMC_RX1.D13@8588,1715 v1(8613,1740) ; FMC_RX1.D13@8588,1715 v1(8613,1690) FMC_RX1.C13@8638,1715 ; FMC_RX1.D10@8588,1865 v1(8613,1890) FMC_RX1.C9@8638,1915 ; FMC_RX1.D7@8588,2015 v1(8613,1990) FMC_RX1.C8@8638,1965 ; FMC_RX1.D3@8588,2215 v1(8613,2240) FMC_RX1.D2@8588,2265 ; FMC_RX1.D3@8588,2215 v1(8613,2190) FMC_RX1.C4@8638,2165 ; FMC_RX1.D3@8588,2215 v1(8563,2240) FMC_RX1.D2@8588,2265 ; FMC_RX1.D2@8588,2265 v1(8613,2290) FMC_RX1.C1@8638,2315 ; v1(8613,940) FMC_RX1.C28@8638,965 ; v1(8613,940) FMC_RX1.C29@8638,915 ; v1(8613,1540) FMC_RX1.C17@8638,1515 ; v1(8613,1740) FMC_RX1.C13@8638,1715 ; v1(8613,1740) FMC_RX1.C12@8638,1765 ; FMC_RX1.C40@8638,365 v1(8663,390) FMC_RX1.B39@8688,415 ; FMC_RX1.C33@8638,715 v1(8663,690) FMC_RX1.B34@8688,665 ; FMC_RX1.C33@8638,715 v1(8663,740) FMC_RX1.C32@8638,765 ; FMC_RX1.C33@8638,715 v1(8613,740) FMC_RX1.C32@8638,765 ; FMC_RX1.C32@8638,765 v1(8663,790) FMC_RX1.B31@8688,815 ; FMC_RX1.C29@8638,915 v1(8663,890) FMC_RX1.B30@8688,865 ; FMC_RX1.C29@8638,915 v1(8663,940) FMC_RX1.C28@8638,965 ; FMC_RX1.C28@8638,965 v1(8663,990) FMC_RX1.B27@8688,1015 ; FMC_RX1.C25@8638,1115 v1(8663,1090) FMC_RX1.B26@8688,1065 ; FMC_RX1.C25@8638,1115 v1(8663,1140) FMC_RX1.C24@8638,1165 ; FMC_RX1.C24@8638,1165 v1(8663,1190) FMC_RX1.B23@8688,1215 ; FMC_RX1.C21@8638,1315 v1(8613,1340) FMC_RX1.C20@8638,1365 ; FMC_RX1.C21@8638,1315 v1(8663,1340) FMC_RX1.C20@8638,1365 ; FMC_RX1.C20@8638,1365 v1(8663,1390) FMC_RX1.B19@8688,1415 ; FMC_RX1.C17@8638,1515 v1(8663,1490) FMC_RX1.B18@8688,1465 ; FMC_RX1.C13@8638,1715 v1(8663,1740) FMC_RX1.C12@8638,1765 ; FMC_RX1.C13@8638,1715 v1(8663,1690) FMC_RX1.B14@8688,1665 v1(8663,1640) FMC_RX1.B15@8688,1615 v1(8713,1590) FMC_RX1.A16@8738,1565 ; FMC_RX1.C12@8638,1765 v1(8663,1790) FMC_RX1.B11@8688,1815 v1(8663,1840) FMC_RX1.B10@8688,1865 v1(8663,1890) FMC_RX1.C9@8638,1915 ; FMC_RX1.C9@8638,1915 v1(8663,1940) FMC_RX1.C8@8638,1965 ; FMC_RX1.C9@8638,1915 v1(8613,1940) FMC_RX1.C8@8638,1965 ; FMC_RX1.C8@8638,1965 v1(8663,1990) FMC_RX1.B7@8688,2015 ; FMC_RX1.C5@8638,2115 v1(8663,2140) FMC_RX1.C4@8638,2165 ; FMC_RX1.C5@8638,2115 v1(8613,2140) FMC_RX1.C4@8638,2165 ; FMC_RX1.C5@8638,2115 v1(8663,2090) FMC_RX1.B6@8688,2065 ; FMC_RX1.C4@8638,2165 v1(8663,2190) FMC_RX1.B3@8688,2215 v1(8663,2240) FMC_RX1.B2@8688,2265 ; FMC_RX1.C1@8638,2315 v1(8663,2290) FMC_RX1.B2@8688,2265 ; v1(8663,440) FMC_RX1.B38@8688,465 ; v1(8663,440) FMC_RX1.B39@8688,415 ; FMC_RX1.B39@8688,415 v1(8713,440) FMC_RX1.B38@8688,465 ; FMC_RX1.B39@8688,415 v1(8713,390) FMC_RX1.A40@8738,365 ; FMC_RX1.B38@8688,465 v1(8713,490) FMC_RX1.A37@8738,515 ; FMC_RX1.B34@8688,665 v1(8713,690) FMC_RX1.A33@8738,715 ; FMC_RX1.B34@8688,665 v1(8713,640) FMC_RX1.B35@8688,615 v1(8713,590) FMC_RX1.A36@8738,565 ; FMC_RX1.B31@8688,815 v1(8663,840) FMC_RX1.B30@8688,865 ; FMC_RX1.B31@8688,815 v1(8713,840) FMC_RX1.B30@8688,865 ; FMC_RX1.B31@8688,815 v1(8713,790) FMC_RX1.A32@8738,765 ; FMC_RX1.B30@8688,865 v1(8713,890) FMC_RX1.A29@8738,915 ; FMC_RX1.B27@8688,1015 v1(8663,1040) FMC_RX1.B26@8688,1065 ; FMC_RX1.B27@8688,1015 v1(8713,990) FMC_RX1.A28@8738,965 ; FMC_RX1.B27@8688,1015 v1(8713,1040) FMC_RX1.B26@8688,1065 ; FMC_RX1.B26@8688,1065 v1(8713,1090) FMC_RX1.A25@8738,1115 ; FMC_RX1.B23@8688,1215 v1(8663,1240) FMC_RX1.B22@8688,1265 ; FMC_RX1.B23@8688,1215 v1(8713,1240) FMC_RX1.B22@8688,1265 ; FMC_RX1.B23@8688,1215 v1(8713,1190) FMC_RX1.A24@8738,1165 ; FMC_RX1.B22@8688,1265 v1(8713,1290) FMC_RX1.A21@8738,1315 ; FMC_RX1.B19@8688,1415 v1(8713,1440) FMC_RX1.B18@8688,1465 ; FMC_RX1.B19@8688,1415 v1(8713,1390) FMC_RX1.A20@8738,1365 v1(8763,1340) FMC_RX1.A21@8738,1315 ; FMC_RX1.B18@8688,1465 v1(8713,1490) FMC_RX1.A17@8738,1515 ; FMC_RX1.B7@8688,2015 v1(8713,1990) FMC_RX1.A8@8738,1965 ; FMC_RX1.B7@8688,2015 v1(8713,2040) FMC_RX1.B6@8688,2065 ; FMC_RX1.B7@8688,2015 v1(8663,2040) FMC_RX1.B6@8688,2065 ; FMC_RX1.B6@8688,2065 v1(8713,2090) FMC_RX1.A5@8738,2115 ; FMC_RX1.B2@8688,2265 v1(8713,2290) FMC_RX1.A1@8738,2315 ; FMC_RX1.A37@8738,515 v1(8763,540) FMC_RX1.A36@8738,565 ; FMC_RX1.A37@8738,515 v1(8713,540) FMC_RX1.A36@8738,565 ; FMC_RX1.A33@8738,715 v1(8713,740) FMC_RX1.A32@8738,765 ; FMC_RX1.A33@8738,715 v1(8763,740) FMC_RX1.A32@8738,765 ; FMC_RX1.A29@8738,915 v1(8713,940) FMC_RX1.A28@8738,965 ; FMC_RX1.A29@8738,915 v1(8763,940) FMC_RX1.A28@8738,965 ; FMC_RX1.A25@8738,1115 v1(8713,1140) FMC_RX1.A24@8738,1165 ; FMC_RX1.A25@8738,1115 v1(8763,1140) FMC_RX1.A24@8738,1165 ; FMC_RX1.A17@8738,1515 v1(8713,1540) FMC_RX1.A16@8738,1565 ; FMC_RX1.A17@8738,1515 v1(8763,1540) FMC_RX1.A16@8738,1565 ; FMC_RX1.A9@8738,1915 v1(8713,1940) FMC_RX1.A8@8738,1965 ; FMC_RX1.A9@8738,1915 v1(8763,1940) FMC_RX1.A8@8738,1965 ; FMC_RX1.A5@8738,2115 v1(8763,2140) FMC_RX1.A4@8738,2165 ; FMC_RX1.A5@8738,2115 v1(8713,2140) FMC_RX1.A4@8738,2165
  Bottom Layer - L10 w19.5: v1(5856,1140) 5891.63,1140 ; C2.2@5861.31,1210.67 R3.1@5861.31,1254.36 ; R12.1@5891.63,1122 C11.2@5891.63,1158
  Bottom Layer - L10 w19.68: C331.1@558,1919.68 v2(558,1942.23) ; C332.1@558,2219.68 v2(558,2242.23) ; C335.1@1022,2219.68 v2(1022,2242.23) ; C337.1@1022,2519.68 v2(1022,2542.23) ; C336.1@1399,2219.68 v2(1399,2242.23) ; C338.1@1399,2519.68 v2(1399,2542.23) ; v2(1498.49,1805.6) C346.2@1519.06,1805.6 ; C339.1@1870,2219.68 v2(1870,2242.23) ; C333.1@1870,2519.68 v2(1870,2542.23) ; C340.1@2247,2219.68 v2(2247,2242.23) ; C334.1@2247,2519.68 v2(2247,2542.23) ; C272.1@3266.68,1160 v2(3289.13,1160) ; C309.1@3611.98,1525 3619.14,1517.84 v3(3619.14,1491.72) ; C291.2@3796.69,1314.47 v1(3796.69,1330.16) C292.1@3796.69,1345.84 ; v1(5083.68,1620.81) v1(5083.68,1736.18)
  Bottom Layer - L10 w21.46: C360.2@495,1942.23 v2(558,1942.23) v2(584.66,1968.88) ; C361.2@495,2242.23 v2(558,2242.23) v2(584.66,2268.88) ; C364.2@959,2242.23 v2(1022,2242.23) v2(1048.66,2268.88) ; C366.2@959,2542.23 v2(1022,2542.23) v2(1048.66,2568.88) ; C365.2@1336,2242.23 v2(1399,2242.23) v2(1425.66,2268.88) ; C367.2@1336,2542.23 v2(1399,2542.23) v2(1425.66,2568.88) ; C368.2@1807,2242.23 v2(1870,2242.23) v2(1896.66,2268.88) ; C362.2@1807,2542.23 v2(1870,2542.23) v2(1896.66,2568.88) ; C369.2@2184,2242.23 v2(2247,2242.23) v2@2273.66,2268.88 ; C363.2@2184,2542.23 v2(2247,2542.23) v2(2273.66,2568.88) ; C266.2@3170.15,1196.02 C266.2@3191.53,1196.02 ; C268.2@3170.15,1464.29 C268.2@3191.53,1464.29 ; C267.1@3262.99,1196.02 C267.1@3284.37,1196.02 ; C269.1@3262.99,1464.29 C269.1@3284.37,1464.29 ; v2(3298.98,1271.2) v2(3298.98,1296.66) ; v2(3298.98,1363.65) v2(3298.98,1389.12)
  Bottom Layer - L10 w22: v3(3492.62,1168.6) C303.2@3492.62,1192.09 ; C305.2@3492.62,1468.22 v3(3492.62,1491.72) ; v3(3619.14,1168.6) C304.1@3619.15,1192.09 ; C306.1@3619.15,1468.22 v3(3619.14,1491.72)
  Bottom Layer - L10 w23.62: v3@2011.9,358.27 U47.2@2011.9,390.55
  Bottom Layer - L10 w24: v3(66,1856.77) C356.2@66,1885.02 ; C391.2@182.12,2286.98 v3(182.12,2315.23) ; C358.2@250,1950.76 v3(250,1979.01) ; v3(312.77,2099) C389.2@341.02,2099 ; C404.2@328,1950.76 v3(328,1979.01) ; C410.2@710.87,856 v3(739.12,856) ; C406.2@804.89,961.86 v3(804.89,990.11) ; C395.2@1031.12,995 v3(1059.37,995) ; C401.2@1181.12,995 v3(1209.37,995) ; C398.2@1331.12,995 v3(1359.37,995) ; v3(2481,599.88) C299.2@2481,628.13 ; v3(2533.47,862.65) C290.2@2533.47,890.9 ; C287.2@2665,693.87 v3(2665,722.12) ; v3(3021.57,923.6) C280.2@3021.57,951.85 ; v3(3250,734.88) C297.2@3250,763.13 ; C276.2@3355.86,670 v3(3384.11,670)
  Bottom Layer - L10 w25: v3(1428.94,836.32) C388.1@1428.94,870.47 ; v3(1459.06,836.32) C388.1@1459.06,870.47 ; v3(1854.94,836.32) C382.2@1854.94,870.47 ; v3(1885.06,836.32) C382.2@1885.06,870.47 ; v3(2369.25,56.82) C194.2@2397.5,56.82 v3(2425.74,56.82) ; v3(3462.62,1168.6) v3(3492.62,1168.6) ; v3(3462.62,1491.72) v3(3492.62,1491.72) ; v3(3619.14,1168.6) v3(3649.14,1168.6) ; v3(3619.14,1491.72) v3(3649.14,1491.72)
  Bottom Layer - L10 w31.5: R49.1@6414.56,2037.44 6548.93,2037.44 ; v9(6458.38,2038.62) v9(6458.38,1991.38) 6548.93,1991.38 ; v9(6505.62,1991.38) v9(6505.62,2038.62) ; C128.2@6548.93,1940 C127.2@6548.93,2090 ; R77.1@7202.56,2037.44 7336.93,2037.44 ; v9(7246.38,2038.62) v9(7246.38,1991.38) 7336.93,1991.38 ; v9(7293.62,1991.38) v9(7293.62,2038.62) ; C161.2@7336.93,1940 C160.2@7336.93,2090
  other v1: 2194.71,33.73 2265.29,33.73 1638.24,76.96 1675.46,76.96 1712.67,76.96 2194.71,92.5 2265.29,92.5 1638.24,112.01 1675.46,112.01 1712.67,112.01 6291.5,251 5921.29,335.96 7805.94,420 7251,517.87 7223.26,622 4497.28,924.59 4865.5,976.44 4965.5,976.44 4344.02,984.2 4426.65,984.2 5609.31,1040 6126.05,1040 6473.85,1040 6523.85,1040 6573.85,1040 6623.85,1040 6673.85,1040 6723.85,1040 6773.85,1040 6823.85,1040 6873.85,1040 6923.85,1040 6973.85,1040 7023.85,1040 7073.85,1040 7173.85,1040 7223.85,1040 7273.85,1040 7323.85,1040 7373.85,1040 7423.85,1040 7473.85,1040 8002.56,1040 3754.2,1043 5540.06,1090 6420.97,1090 6923.47,1090 6974.53,1090 7423.85,1090 7473.85,1090 7525.03,1090 5595,1115 6136.53,1140 6424,1140 6474,1140 6923.47,1140 6974.53,1140 7423.85,1140 7473.85,1140 7523.85,1140 4641,1168.84 6136.53,1190 6424,1190 6474,1190 6923.47,1190 6974.53,1190 7423.85,1190 7473.85,1190 7523.85,1190 7726,1190 7785,1190 5600,1215 4641,1215.89 4731,1227.89 3828.43,1229.32 5856,1232.52 6424,1240 6923.47,1240 6949,1240 6974.53,1240 7423.85,1240 7523.85,1240 7726,1240 7785,1240 4731,1274.95 4641,1286.95 6472.15,1290 6949,1290 7423.85,1290 4641,1334 7423.85,1340 7473.85,1340 4731,1346 6744.39,1390 6794.39,1390 6844.39,1390 7053.61,1390 7103.61,1390 7153.61,1390 7710,1390 7844,1390 4731,1393.06 5524.31,1397.5 4641,1405.06 6744.39,1440 6794.39,1440 6844.39,1440 7053.61,1440 7103.61,1440 7153.61,1440 7710,1440 7844,1440 4641,1452.11 4731,1464.11 6744.39,1490 6794.39,1490 6844.39,1490 6879.26,1490 6914.13,1490 6949,1490 6983.87,1490 7018.74,1490 7053.61,1490 7103.61,1490 7153.61,1490 4731,1511.17 5337.65,1540 6744.39,1540 6794.39,1540 6844.39,1540 6879.26,1540 6914.13,1540 6949,1540 6983.87,1540 7018.74,1540 7053.61,1540 7103.61,1540 7153.61,1540 4723.47,1544.09 3927.57,1562.43 5414.55,1584.68 5531.92,1584.68 6744.39,1590 6794.39,1590 6844.39,1590 7053.61,1590 7103.61,1590 7153.61,1590 4951.82,1603.5 3932.82,1618.62 4597,1619 5020.05,1620.81 3477.65,1630.95 8134.5,1633.3 8159.8,1633.3 4470.64,1637 6744.39,1640 6794.39,1640 6844.39,1640 7053.61,1640 7103.61,1640 7153.61,1640 4677.54,1653.5 3477.65,1659.95 3932.82,1660.67 4035,1668.13 5776,1679.37 6070.47,1679.37 8134.5,1684.2 8159.8,1684.2 3477.65,1688.95 6629,1690 6679,1690 7219,1690 7269,1690 3348.58,1709.95 3373.58,1709.95 5705.33,1712.23 5638.33,1721.1 4361.81,1723.61 4408.86,1723.61 4710.54,1736.5 5020.05,1736.18 6629,1740 6679,1740 6729,1740 6877,1740 6925,1740 7020,1740 7070,1740 7169,1740 7219,1740 7269,1740 4087.91,1743.81 4554.36,1788.53 4832,1790 4925,1790 8070.38,1790 4288.96,1809.5 4343.01,1809.5 4218.92,1811 4032.95,1837.32 4126.58,1837.31 4251.3,1838.05 4554.36,1840 5583.65,1840 6005.91,1840 4709,1841.77 5084.68,1843.81 5583.65,1890 7031.56,1890 5331.35,1940 5521.12,1940 5949,1940 5084.68,1990 3476.21,2048.5 3523.9,2048.5 4555.06,2119.97 3460.69,2141.68 6281.44,2150 6438.69,2150 7069.44,2150 7226.69,2150 4555.06,2174.02 5413.31,2179.37 5393.63,2235.37 5954,2242.56 3871.1,2257 5978.12,2292.5 6623.79,2334.81 6757.46,2334.81 6891.13,2334.81 5779.88,2341.5 5978.12,2341.5 6026,2372.62 6202.68,2390.44 5718.44,2406.01 6623.79,2436 6757.46,2436 6891.13,2436 7145,2436 7195,2436 6494.68,2464.56 7547.5,2486.37 6494.68,2511.44 6623.79,2537.19 6757.46,2537.19 6891.13,2537.19 7291,2563.95 7294.56,2612
  other v2: 3024.02,1170.32 1743,1190.53 1777,1190.53 1889,1190.53 1923,1190.53 3168.07,1196.02 3193.53,1196.02 3260.91,1196.02 3286.37,1196.02 1743,1277.34 1777,1277.34 1889,1277.34 1923,1277.34 265,1315.79 1743,1382.97 1777,1382.97 1889,1382.97 1923,1382.97 3170.07,1464.29 3193.53,1464.29 3260.91,1464.29 3286.37,1464.29 1743,1469.79 1777,1469.79 1889,1469.79 1923,1469.79 3024.02,1490 247.33,1545.12 405,1571.63 446.68,1571.63 292.69,1694 342,1696.88 807.48,1900 495,1975.88 807.48,2200 1271.48,2200 495,2275.88 959,2275.88 1336,2275.88 1807,2275.88 2184,2275.88 1271.48,2500 2119.48,2500 959,2575.88 1336,2575.88 1807,2575.88 2184,2575.88
  other v3: 2011.9,358.37 2019.99,724.16 2708.99,724.16 1661.88,774.76 1692,774.76 1722.12,774.76 2019.99,782.16 2708.99,782.16 1676.94,804.88 1707.06,804.88 944.5,827.97 1007.5,827.97 1094.5,827.97 1157.5,827.97 1244.5,827.97 1307.5,827.97 1676.94,835 1707.06,835 944.5,862.03 1007.5,862.03 1094.5,862.03 1157.5,862.03 1244.5,862.03 1307.5,862.03 2134.99,878.02 2238.99,878.02 2823.99,878.02 2927.99,878.02 1676.94,1003 1707.06,1003 1661.88,1033.12 1692,1033.12 1722.12,1033.12 317.48,2283
  other v4: 1692,886.52 1668.38,919 1715.62,919 1692,951.48 4109.75,1192.36 4158.96,1192.36 4208.17,1192.36 4257.39,1192.36 4306.6,1192.36 4355.81,1192.36 4405.02,1192.36 4109.75,1241.57 4158.96,1241.57 4208.17,1241.57 4257.39,1241.57 4306.6,1241.57 4355.81,1241.57 4405.02,1241.57 4109.75,1290.79 4158.96,1290.79 4208.17,1290.79 4257.39,1290.79 4306.6,1290.79 4355.81,1290.79 4405.02,1290.79 4109.75,1340 4158.96,1340 4208.17,1340 4257.39,1340 4306.6,1340 4355.81,1340 4405.02,1340 4109.75,1389.21 4158.96,1389.21 4208.17,1389.21 4257.39,1389.21 4306.6,1389.21 4355.81,1389.21 4405.02,1389.21 4109.75,1438.43 4158.96,1438.43 4208.17,1438.43 4257.39,1438.43 4306.6,1438.43 4355.81,1438.43 4405.02,1438.43 4109.75,1487.64 4158.96,1487.64 4208.17,1487.64 4257.39,1487.64 4306.6,1487.64 4355.81,1487.64 4405.02,1487.64 5386.87,1740 5426.24,1740 5465.61,1740 5386.87,1790 5465.61,1790 5386.87,1840 5426.24,1840 5465.61,1840 4131.34,2015.5 4188.82,2015.5 4246.3,2015.5 4303.78,2015.5 4086.06,2060.78 4131.34,2060.78 4188.82,2060.78 4246.3,2060.78 4303.78,2060.78 4349.06,2060.78 4086.06,2118.26 4131.34,2118.26 4188.82,2118.26 4246.3,2118.26 4303.78,2118.26 4349.06,2118.26 4086.06,2175.74 4131.34,2175.74 4188.82,2175.74 4246.3,2175.74 4303.78,2175.74 4349.06,2175.74 4086.06,2233.22 4131.34,2233.22 4188.82,2233.22 4246.3,2233.22 4303.78,2233.22 4349.06,2233.22 4131.34,2278.5 4188.82,2278.5 4246.3,2278.5 4303.78,2278.5 6309.3,2448.63 6348.68,2448.63 6388.05,2448.63 6309.3,2488 6348.68,2488 6388.05,2488 6309.3,2527.37 6348.68,2527.37 6388.05,2527.37
  other v6: 29,1064 100,1064 171,1064 29,1141 100,1141 171,1141 7866.98,1190 7892.99,1190 7919,1190 7945.01,1190 7971.02,1190 7866.98,1240 7892.99,1240 7919,1240 7945.01,1240 7971.02,1240 29,1409 100,1409 171,1409 29,1486 100,1486 171,1486
  other v10: 4640.28,749.51 4600.91,796.76 4640.28,796.76 4679.65,796.76 4640.28,844
GND2: C118.2 C119.2 C131.2 C132.2 C133.2 C134.2 C135.2 C136.2 C137.2 C138.2 C139.2 C140.2 C141.2 C142.2 C200.2 C201.2 C205.2 C210.2 C211.2 C212.1 C214.2 L23.1 R67.1 R112.1 U13.1 U13.5 U13.10 U13.11 U13.13 U13.15 U13.25 U13.35 U13.47 U13.51 U14.2 U14.4 U15.5 USB.5 USB.6 USB.7 USB.8 USB.9 | length 1319.2
  Top Layer L1 w8: U13.51@6037.74,706.5 6037.74,662.04 v1(6042.74,657.04)
  Top Layer L1 w10: v1(5656.5,645.48) 5666.34,635.64 U13.1@5710.97,635.64 ; U13.15@5710.97,360.05 v1(5765,360.05) ; U13.13@5710.97,399.42 v1(5765,399.42) ; U13.11@5710.97,438.79 5755.59,438.79 v1(5765.44,448.63) 5755.59,458.47 U13.10@5710.97,458.47 ; U13.5@5710.97,556.9 v1(5765,556.9) ; v1(5929.47,215.03) 5939.31,224.87 U13.25@5939.31,269.5 ; v1(6093.51,379.73) U13.35@6147.98,379.73 C134.2@6202.44,379.73 ; v1(6093.51,615.95) U13.47@6147.98,615.95 ; C134.2@6202.44,381.5 6208.5,381.5 v1(6215,375)
  Top Layer L1 w16.5: v1(5565,947.84) 5565,932.66 C137.2@5571.66,926 C135.2@5619.28,926 5615,930.28 v1(5615,947.84) ; C133.2@5609.46,419.1 5609.46,404.7 v1(5615,399.16) ; C140.2@5609.46,468.32 5609.46,453.91 v1(5615,448.37) ; C142.2@5609.46,566.74 5609.46,581.14 v1(5615,586.68) ; C136.2@5765,808.01 v1(5765,829.07) ; C118.2@5876.72,215.03 v1(5897.77,215.03) ; v1(5965.3,801.51) C132.2@5965.3,781.24 C214.2@6021.6,781.24 v1(6021.6,801.51) ; C119.2@6104.46,210.03 v1(6125.52,210.03) ; C131.2@6218.44,571.41 v1(6218.44,592.47)
  Top Layer L1 w19.5: USB.5@330.71,719.44 v1(387.98,719.45)
  Top Layer L1 w24: v1(5521.74,603.08) R67.1@5550.47,603.08
  Bottom Layer - L10 w16.5: v1(275.94,670.86) 320.38,670.86 v1(329.24,662) ; v1@6093.51,616.47 6076.68,616.47 U15.5@6076.68,605.39 6131.17,605.39 C205.2@6142,594.56
  Bottom Layer - L10 w18: v1(5965.3,801.51) 5965.3,841.38 C212.1@5969.91,846
  Bottom Layer - L10 w24: C139.2@5608.19,477.1 5615,470.29 v1(5615,448.37) ; v1(5615,586.68) 5634.32,606 C141.2@5637.44,606
  other v1: 6228.5,251 5510.91,300.8 110.24,607.24 326.77,607.24 181.46,633.46 256.26,775.86 5993.45,781.24 6165,789.7 138.86,839 110.24,957.63 326.77,957.63
IN_N: C295.2 K5.2 R203.1 | length 490
  Bottom Layer - L10 w8: K5.2@2643,1230.16 2694,1179.16 2863,1179.16 2998.32,1314.47 R203.1@3024.02,1314.47 C295.2@3024.02,1282.69
IN_P: C296.2 K5.7 R169.2 | length 390
  Bottom Layer - L10 w8: K5.7@2743,1430.16 2794,1481.16 2863,1481.16 2998.32,1345.84 R169.2@3024.02,1345.84 C296.2@3024.02,1377.63
K1_AX: K1.5 K1_Ax.1 U27.16 | length 1084.9
  Top Layer L1 w8: K1.5@315,1330.16 385.71,1330.16 465,1409.45 465,1476.16 539.84,1551 671,1551 K1_Ax.1@735,1615
  Bottom Layer - L10 w8: K1_Ax.1@735,1615 735,1674.43 1006.14,1945.57 U27.16@1071.14,1945.57
K1_AX_LED: K8.6 R259.2 | length 68.4
  Top Layer L1 w8: K8.6@4239,376 R259.2@4307.44,376
K1_BX: K1.10 K1_Bx.1 U27.15 | length 825.1
  Top Layer L1 w8: K1.10@615,1330.16 835,1550.16 K1_Bx.1@835,1615
  Bottom Layer - L10 w8: K1_Bx.1@835,1615 835,1728.83 1026.14,1919.98 U27.15@1091.14,1919.98
K1_BX_LED: K8.1 R260.2 | length 68.4
  Top Layer L1 w8: K8.1@3739,376 R260.2@3807.44,376
K2_AX: K2.5 K2_Ax.1 U27.14 | length 1099.7
  Top Layer L1 w8: 834,1468 834,1310.45 864.29,1280.16 905.71,1280.16 955.71,1330.16 K2.5@1185,1330.16 ; 835,1469 935,1569 K2_Ax.1@935,1615
  Bottom Layer - L10 w8: K2_Ax.1@935,1615 935,1783.24 1046.14,1894.39 U27.14@1091.14,1894.39
K2_AX_LED: K7.1 R261.2 | length 68.4
  Top Layer L1 w8: R261.2@3114,307.56 K7.1@3114,376
K2_BX: K2.10 K2_Bx.1 U27.13 | length 638.7
  Top Layer L1 w8: K2.10@885,1330.16 935,1380.16 935,1476.16 1035,1576.16 K2_Bx.1@1035,1615
  Bottom Layer - L10 w8: K2_Bx.1@1035,1615 1035,1837.65 1066.14,1868.8 U27.13@1091.14,1868.8
K2_BX_LED: K7.6 R262.2 | length 68.4
  Top Layer L1 w8: R262.2@3545.56,376 K7.6@3614,376
K3_AX: K3.5 K3_Ax.1 U27.12 | length 652.7
  Top Layer L1 w8: K3_Ax.1@1147,1615 1147,1576.16 K3.5@1393,1330.16
  Bottom Layer - L10 w8: U27.12@1091.14,1843.2 1116.14,1843.2 1147,1812.35 K3_Ax.1@1147,1615
K3_AX_LED: K6.1 R263.2 | length 68.4
  Top Layer L1 w8: K6.1@2489,376 R263.2@2557.44,376
K3_BX: K3.10 K3_Bx.1 U29.16 | length 1049.9
  Top Layer L1 w8: K3.10@1693,1330.16 1643,1380.16 1643,1480.16 1777.84,1615 K3_Bx.1@1973,1615
  Bottom Layer - L10 w8: K3_Bx.1@1973,1615 2159,1801 2159,1897 2208,1946 U29.16@2273,1946
K3_BX_LED: K6.6 R264.2 | length 68.4
  Top Layer L1 w8: R264.2@2989,307.56 K6.6@2989,376
K4_AX: K4.5 K4_Ax.1 U29.15 | length 740.9
  Top Layer L1 w8: K4.5@1973,1330.16 2023,1380.16 2023,1565 K4_Ax.1@2073,1615
  Bottom Layer - L10 w8: K4_Ax.1@2073,1615 2191,1733 2191,1883.41 2228,1920.41 U29.15@2273,1920.41
K4_BX: K4.10 K4_Bx.1 U29.14 | length 620.7
  Top Layer L1 w8: K4_Bx.1@2223,1615 2223,1380.16 K4.10@2273,1330.16
  Bottom Layer - L10 w8: K4_Bx.1@2223,1615 2223,1869.82 2248,1894.82 U29.14@2273,1894.82
K5_AX: K5.5 K5_Ax.1 U29.13 | length 910
  Top Layer L1 w8: K5_Ax.1@2473,1615 2658.16,1615 2793,1480.16 2793,1380.16 K5.5@2843,1330.16
  Bottom Layer - L10 w8: U29.13@2273,1869.23 2318,1869.23 2423,1764.23 2423,1665 K5_Ax.1@2473,1615
K5_BX: K5.10 K5_Bx.1 U29.12 | length 640
  Top Layer L1 w8: K5_Bx.1@2323,1615 2323,1550.16 K5.10@2543,1330.16
  Bottom Layer - L10 w8: U29.12@2273,1843.64 2298,1843.64 2323,1818.64 K5_Bx.1@2323,1615
LM95233_SMBCLK: R32.1 R125.1 R127.1 U3.13 | length 2012.8
  Top Layer L1 w9: U3.13@4715.08,836.13 4735.28,836.13 v1(4737.28,838.13)
  Signals - L8 w4: v1(4737.28,838.13) 4715.08,815.93 4715.08,802.92 4740,778 4776,778 4789.44,791.44 5844.89,791.44 5917.33,719 6125,719 6235,609 6235,432 6269.87,397.13 v1(6308.56,397.13)
  Bottom Layer - L10 w8: v1(4737.28,838.13) 4744.15,845 4783.91,845 R32.1@4797.72,858.81
LM95233_SMBDAT: R31.1 R117.1 R124.1 R126.1 U3.12 | length 2085
  Top Layer L1 w8: R124.1@6257,397.13 6257.44,397.57 v1(6257.44,445)
  Top Layer L1 w9: U3.12@4715.08,816.44 4735.28,816.44 v1(4737.28,814.44)
  Signals - L8 w4: v1(4737.28,814.44) 4794.46,871.62 6023.38,871.62 6257.44,637.56 v1(6257.44,445)
  Bottom Layer - L10 w8: v1(4737.28,814.44) 4748.96,814.44 4755.99,821.47 4787.66,821.47 R31.1@4797.72,811.41 ; R117.1@6181.81,392.13 6231.13,392.13 6257.44,418.44 v1(6257.44,445)
LMH_SCLK: U23.14 U24.14 | length 2292.9
  Bottom Layer - L10 w8: U23.14@3565.72,1275.04 3565.72,1164.65 3641,1089.37 3641,633 3689,585 4973.55,585 5130.94,742.39 U24.14@5175.57,742.39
